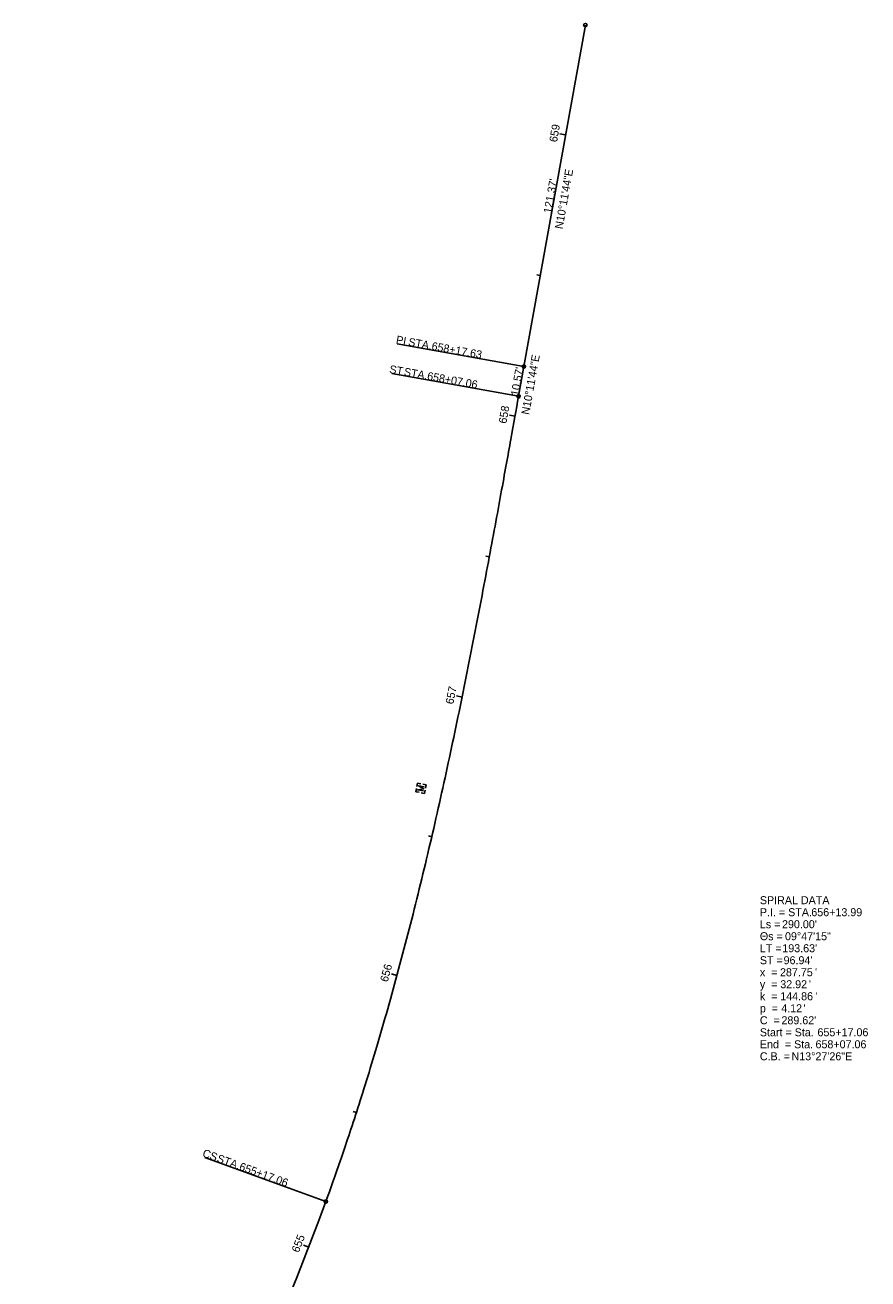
# Model space of a CAD drawing. Extents: x 171681 to 172332, y 456784 to 458794.
# Drawn here: x 171956.4 to 172251.2, y 457222.2 to 457660.8 of the extents above; entities that cross this region are included whole.
import ezdxf

# ---------------------------------------------------------------- set-up
doc = ezdxf.new("R2010")
doc.units = 0
for name, color, linetype in [('GE_X_Alignment', 7, 'Continuous'), ('GE_X_Alignment_100_Bearings', 7, 'Continuous'), ('GE_X_Alignment_100_Cardinal_Points', 7, 'Continuous'), ('GE_X_Alignment_100_Curve_Data', 7, 'Continuous'), ('GE_X_Alignment_100_Distances', 7, 'Continuous'), ('GE_X_Alignment_100_Stations', 7, 'Continuous'), ('SV_X_Mon_Cells_Found', 7, 'Continuous')]:
    doc.layers.add(name, color=color, linetype=linetype)

msp = doc.modelspace()

# ---------------------------------------------------------------- linework, layer by layer
at = {"layer": 'GE_X_Alignment'}
for p, q in [((172130.9, 457541.32), (172152.38, 457660.78)), ((172130.9, 457541.32), (172152.38, 457660.78)), ((172130.9, 457541.32), (172152.38, 457660.78)), ((172129.03, 457530.92), (172130.9, 457541.32)), ((172129.03, 457530.92), (172130.9, 457541.32))]:
    msp.add_line(p, q, dxfattribs=at)
msp.add_arc((171263.9, 457539.33), 848.83, 324.67218, 340.01698, dxfattribs=at)
msp.add_arc((171263.9, 457539.33), 848.83, 324.67218, 340.01698, dxfattribs=at)
msp.add_arc((171263.9, 457539.33), 848.83, 324.67218, 340.01698, dxfattribs=at)
msp.add_open_spline([(172061.63, 457249.25), (172063.28, 457253.79), (172066.5, 457262.9), (172072.66, 457281.23), (172079.82, 457304.31), (172087.66, 457332.24), (172094.83, 457360.34), (172101.42, 457388.58), (172107.52, 457416.93), (172113.24, 457445.37), (172118.66, 457473.85), (172123.02, 457497.62), (172126.46, 457516.65), (172128.17, 457526.16), (172129.03, 457530.92)], degree=3, dxfattribs=at)
msp.add_open_spline([(172061.63, 457249.25), (172063.28, 457253.79), (172066.5, 457262.9), (172072.66, 457281.23), (172079.82, 457304.31), (172087.66, 457332.24), (172094.83, 457360.34), (172101.42, 457388.58), (172107.52, 457416.93), (172113.24, 457445.37), (172118.66, 457473.85), (172123.02, 457497.62), (172126.46, 457516.65), (172128.17, 457526.16), (172129.03, 457530.92)], degree=3, dxfattribs=at)
msp.add_open_spline([(172061.63, 457249.25), (172063.28, 457253.79), (172066.5, 457262.9), (172072.66, 457281.23), (172079.82, 457304.31), (172087.66, 457332.24), (172094.83, 457360.34), (172101.42, 457388.58), (172107.52, 457416.93), (172113.24, 457445.37), (172118.66, 457473.85), (172123.02, 457497.62), (172126.46, 457516.65), (172128.17, 457526.16), (172129.03, 457530.92)], degree=3, dxfattribs=at)
at = {"layer": 'GE_X_Alignment_100_Cardinal_Points'}
for p, q in [((172130.9, 457541.32), (172086.61, 457549.29)), ((172129.03, 457530.92), (172084.74, 457538.89)), ((172061.63, 457249.25), (172019.34, 457264.63))]:
    msp.add_line(p, q, dxfattribs=at)
for centre in [(172152.38, 457660.78), (172130.9, 457541.32), (172129.03, 457530.92), (172061.63, 457249.25)]:
    msp.add_circle(centre, 0.6, dxfattribs=at)
at = {"layer": 'GE_X_Alignment_100_Stations'}
for p, q in [((172145.48, 457622.4), (172143.51, 457622.75)), ((172136.63, 457573.18), (172135.45, 457573.4)), ((172127.78, 457523.97), (172125.81, 457524.33)), ((172118.8, 457474.79), (172117.63, 457475.01)), ((172109.26, 457425.71), (172107.3, 457426.11)), ((172098.65, 457376.85), (172097.48, 457377.12)), ((172086.49, 457328.35), (172084.56, 457328.87)), ((172072.3, 457280.41), (172071.16, 457280.78)), ((172055.64, 457233.28), (172053.77, 457234))]:
    msp.add_line(p, q, dxfattribs=at)
at = {"layer": 'SV_X_Mon_Cells_Found'}
msp.add_line((172094.9, 457393.8), (172094.9, 457393.8), dxfattribs=at)
for points in [[(172093.49, 457394.43), (172093.71, 457395.56), (172094.81, 457395.35)], [(172095.74, 457392.89), (172093.78, 457393.26), (172095.88, 457393.61), (172094.06, 457394.71), (172096.02, 457394.34)], [(172095.55, 457395.2), (172096.66, 457394.99), (172096.44, 457393.87)], [(172094.25, 457392.4), (172093.14, 457392.61), (172093.35, 457393.71)], [(172096.3, 457393.15), (172096.09, 457392.04), (172094.99, 457392.26)]]:
    msp.add_lwpolyline(points, dxfattribs=at)

# ---------------------------------------------------------------- texts
at = {"layer": 'GE_X_Alignment_100_Bearings'}
for p in [(172144.4, 457589.26), (172132.72, 457524.33)]:
    msp.add_text('N10°11\'44"E', height=2.8, rotation=79.8044, dxfattribs=at).set_placement(p)
at = {"layer": 'GE_X_Alignment_100_Cardinal_Points'}
for s, rotation, p in [('PI', 349.8044, (172086, 457549.44)), (' STA. ', 349.8044, (172089.27, 457548.85)), ('658+17.63', 349.8044, (172098.44, 457547.2)), ('ST', 349.8044, (172083.68, 457539.11)), (' STA. ', 349.8044, (172087.73, 457538.39)), ('658+07.06', 349.8044, (172096.9, 457536.73)), ('CS', 340.017, (172018.22, 457265.07)), (' STA. ', 340.017, (172022.31, 457263.58)), ('655+17.06', 340.017, (172031.08, 457260.4))]:
    msp.add_text(s, height=2.8, rotation=rotation, dxfattribs=at).set_placement(p)
at = {"layer": 'GE_X_Alignment_100_Curve_Data'}
for s, p in [('SPIRAL DATA', (172213.42, 457353.26)), ('P.I. = STA. ', (172213.42, 457349.06)), ('656+13.99', (172231.41, 457349.06)), ('Ls = ', (172213.42, 457344.86)), ("290.00'", (172221.17, 457344.86)), ('Θs = ', (172213.42, 457340.66)), ('09°47\'15"', (172222.21, 457340.66)), ('LT = ', (172213.42, 457336.46)), ("193.63'", (172221.27, 457336.46)), ('ST = ', (172213.42, 457332.26)), ("96.94'", (172221.72, 457332.26)), ('x  = ', (172213.42, 457328.06)), ('287.75', (172220.46, 457328.06)), ("'", (172232.71, 457328.06)), ('y  = ', (172213.42, 457323.86)), ('32.92', (172220.56, 457323.86)), ("'", (172230.57, 457323.86)), ('k  = ', (172213.42, 457319.66)), ('144.86', (172220.56, 457319.66)), ("'", (172232.81, 457319.66)), ('p  = ', (172213.42, 457315.46)), ('4.12', (172220.9, 457315.46)), ("'", (172228.68, 457315.46)), ('C  = ', (172213.42, 457311.26)), ("289.62'", (172220.97, 457311.26)), ('Start = Sta. ', (172213.42, 457307.06)), ('655+17.06', (172233.57, 457307.06)), ('End  = Sta. ', (172213.42, 457302.86)), ('658+07.06', (172232.88, 457302.86)), ('C.B. = ', (172213.42, 457298.66)), ('N13°27\'26"E', (172224.49, 457298.66))]:
    msp.add_text(s, height=2.8, dxfattribs=at).set_placement(p)
at = {"layer": 'GE_X_Alignment_100_Distances'}
for s, p in [("121.37'", (172140.47, 457594.72)), ("10.57'", (172128.99, 457530.89))]:
    msp.add_text(s, height=2.8, rotation=79.8044, dxfattribs=at).set_placement(p)
at = {"layer": 'GE_X_Alignment_100_Stations'}
for s, rotation, p in [('659', 79.8044, (172142.45, 457619.66)), ('658', 79.7986, (172124.74, 457521.22)), ('657', 78.4706, (172106.16, 457423.03)), ('656', 74.815, (172083.23, 457325.86)), ('655', 68.8656, (172052.15, 457231.19))]:
    msp.add_text(s, height=2.8, rotation=rotation, dxfattribs=at).set_placement(p)

doc.saveas('drawing.dxf')
